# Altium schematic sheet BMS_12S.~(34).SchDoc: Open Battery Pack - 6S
size A3; Author: Morgane Vallée; Revision: 1.0; SheetNumber: 3; SheetTotal: 4
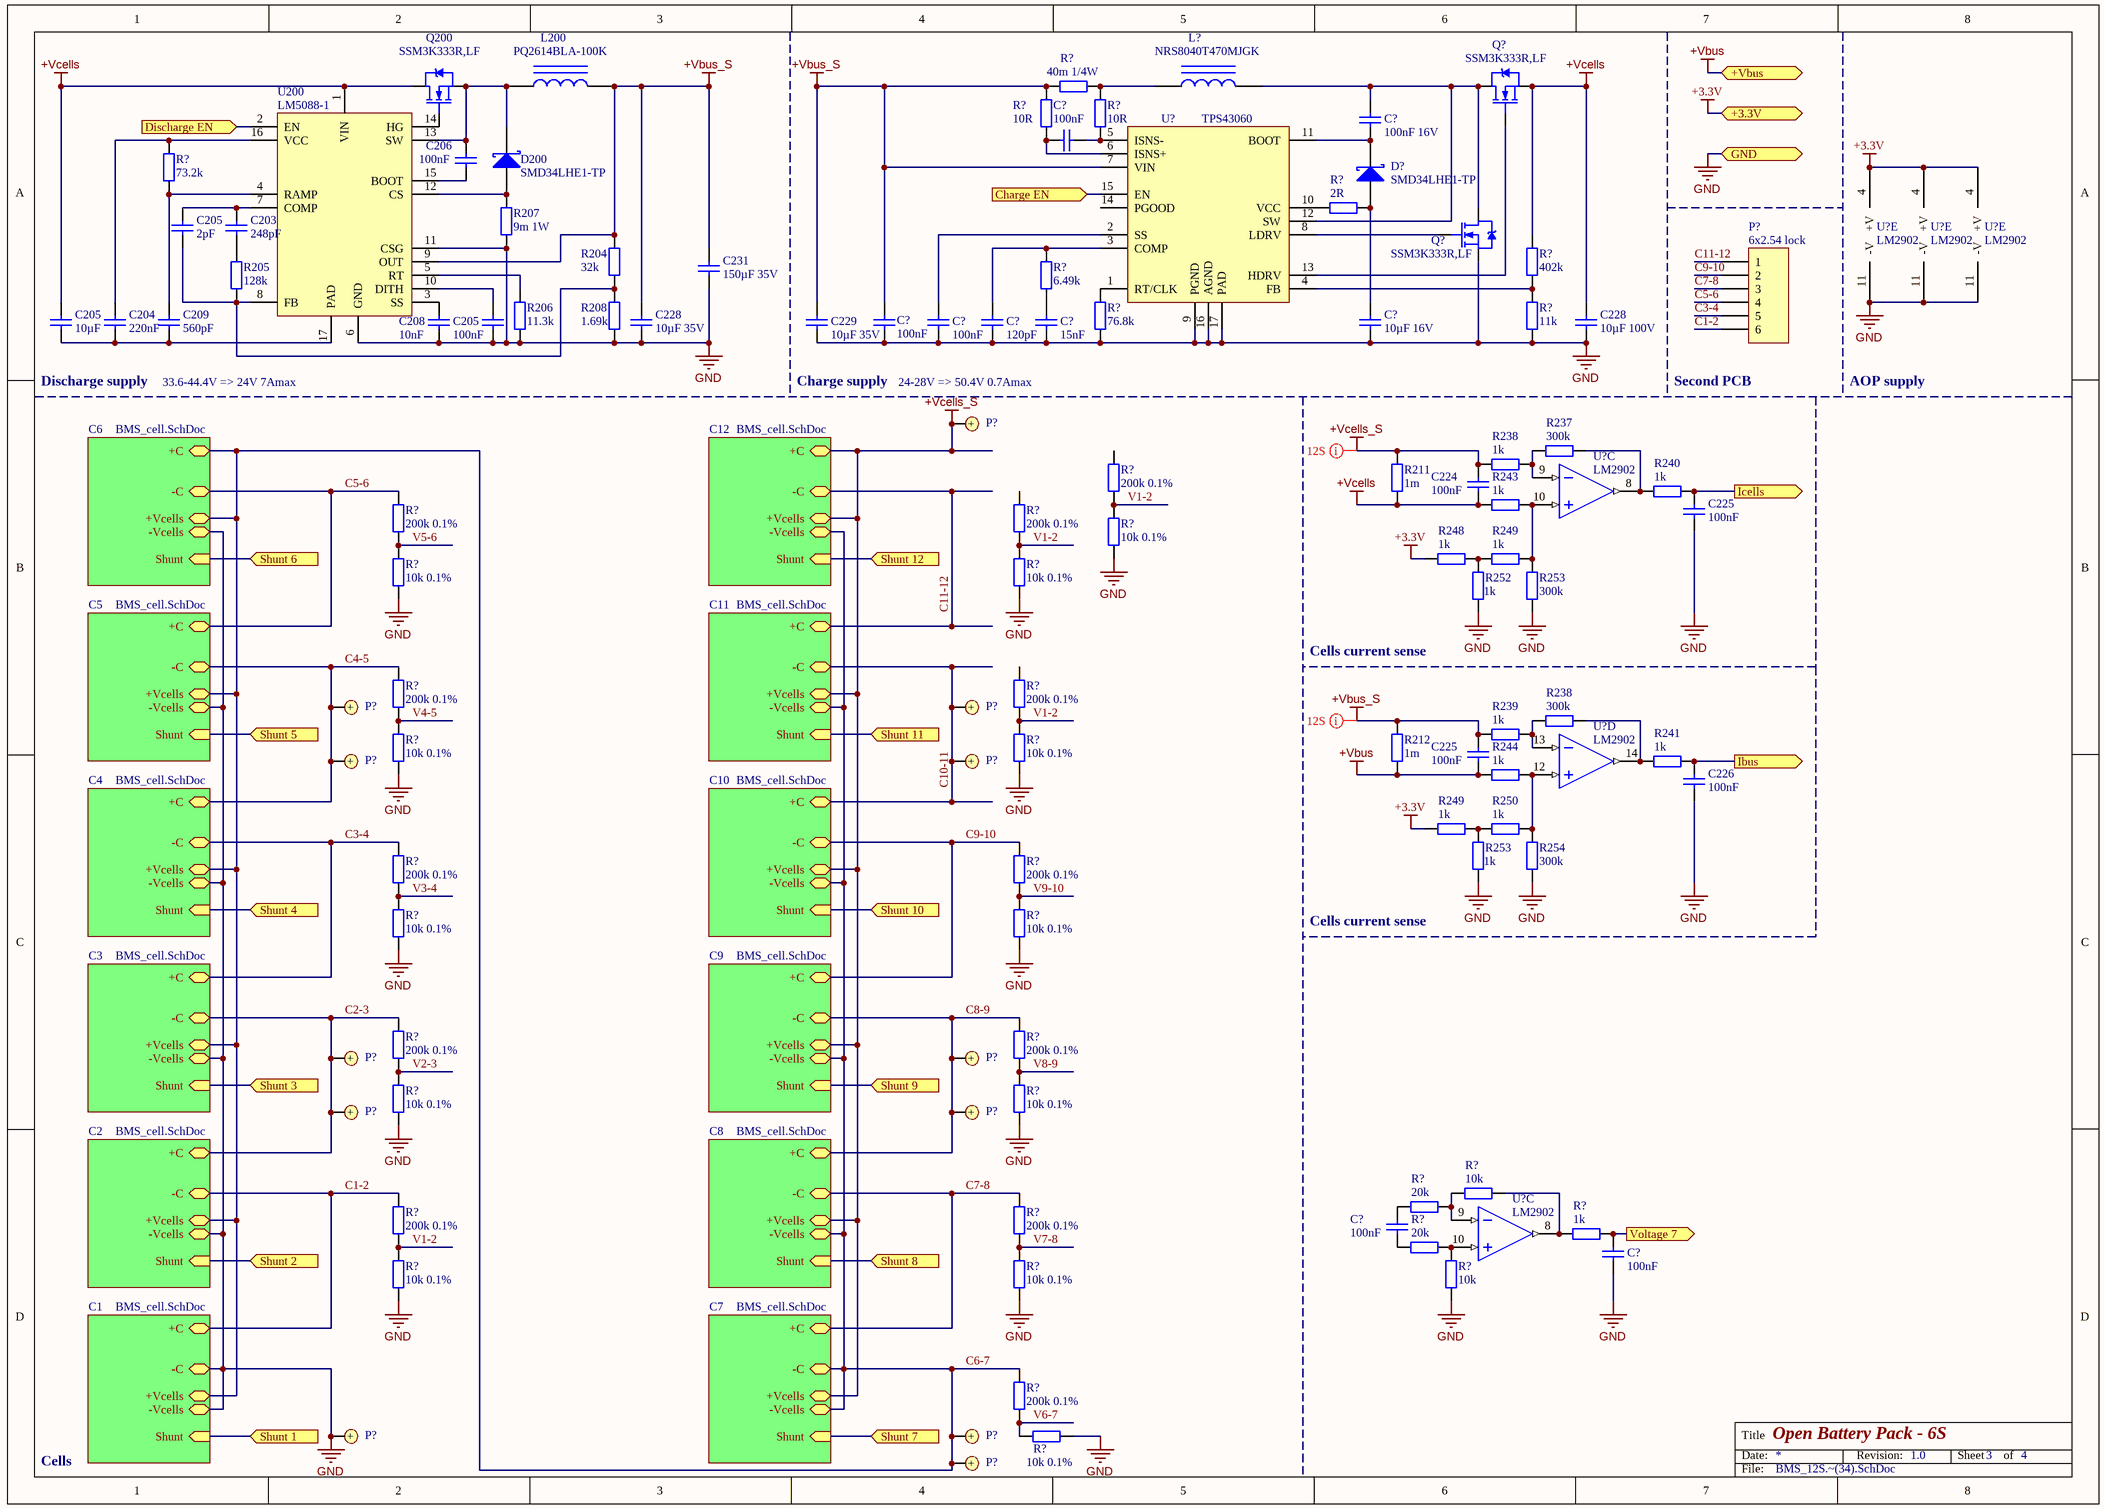
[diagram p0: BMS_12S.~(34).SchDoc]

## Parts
(Parts that share a designator on the sheet are numbered #1, #2 ... from top to bottom, then left to right.)
C203  248pF  [C0603]
C204  220nF  [C0603]
C205#1  2pF  [C0603]
C205#2  10µF  [C0603]
C205#3  100nF  [C0603]
C206  100nF  [C0603]
C208  10nF  [C0603]
C209  560pF  [C0603]
C224  100nF  [C0603]
C225#1  100nF  [C0603]
C225#2  100nF  [C0603]
C226  100nF  [C0603]
C228#1  10µF 35V  [C0603]
C228#2  10µF 100V  [C0603]
C229  10µF 35V  [C0603]
C231  150µF 35V  [C0603]
C?#1  100nF 16V  [C0603]
C?#2  100nF  [C0603]
C?#3  100nF  [C0603]
C?#4  120pF  [C0603]
C?#5  15nF  [C0603]
C?#6  10µF 16V  [C0805]
C?#7  100nF  [C0603]
C?#8  100nF  [C0603]
C?#9  100nF  [C0603]
D200  SMD34LHE1-TP  [SOD-123H]
D?  SMD34LHE1-TP  [SOD-123H]
L200  PQ2614BLA-100K  [SELF_SMD_8x8]
L?  NRS8040T470MJGK  [SELF_SMD_8x8]
P?#1  6x2.54 lock  [MOLEX KK 0022272061]
P?#2  Bat+  [Keystone 241]  (value not drawn)
P?#3  Bat+  [Keystone 241]  (value not drawn)
P?#4  Bat+  [Keystone 241]  (value not drawn)
P?#5  Bat+  [Keystone 241]  (value not drawn)
P?#6  Bat+  [Keystone 241]  (value not drawn)
P?#7  Bat+  [Keystone 241]  (value not drawn)
P?#8  Bat+  [Keystone 241]  (value not drawn)
P?#9  Bat+  [Keystone 241]  (value not drawn)
P?#10  Bat+  [Keystone 241]  (value not drawn)
P?#11  Bat+  [Keystone 241]  (value not drawn)
P?#12  Bat+  [Keystone 241]  (value not drawn)
P?#13  Bat+  [Keystone 241]  (value not drawn)
Q200  SSM3K333R,LF  [TI SOT-23-3 DBZ]
Q?#1  SSM3K333R,LF  [TI SOT-23-3 DBZ]
Q?#2  SSM3K333R,LF  [TI SOT-23-3 DBZ]
R204  32k  [R0603]
R205  128k  [R0603]
R206  11.3k  [R0603]
R207  9m 1W  [R1206]
R208  1.69k  [R0603]
R211  1m  [R1206]
R212  1m  [R1206]
R237  300k  [R0603]
R238#1  1k  [R0603]
R238#2  300k  [R0603]
R239  1k  [R0603]
R240  1k  [R0603]
R241  1k  [R0603]
R243  1k  [R0603]
R244  1k  [R0603]
R248  1k  [R0603]
R249#1  1k  [R0603]
R249#2  1k  [R0603]
R250  1k  [R0603]
R252  1k  [R0603]
R253#1  300k  [R0603]
R253#2  1k  [R0603]
R254  300k  [R0603]
R?#1  10R  [R0603]
R?#2  40m 1/4W  [R1206]
R?#3  10R  [R0603]
R?#4  73.2k  [R0603]
R?#5  2R  [R0603]
R?#6  402k  [R0603]
R?#7  6.49k  [R0603]
R?#8  76.8k  [R0603]
R?#9  11k  [R0603]
R?#10  200k 0.1%  [R0603]
R?#11  200k 0.1%  [R0603]
R?#12  200k 0.1%  [R0603]
R?#13  10k 0.1%  [R0603]
R?#14  10k 0.1%  [R0603]
R?#15  10k 0.1%  [R0603]
R?#16  200k 0.1%  [R0603]
R?#17  200k 0.1%  [R0603]
R?#18  10k 0.1%  [R0603]
R?#19  10k 0.1%  [R0603]
R?#20  200k 0.1%  [R0603]
R?#21  200k 0.1%  [R0603]
R?#22  10k 0.1%  [R0603]
R?#23  10k 0.1%  [R0603]
R?#24  200k 0.1%  [R0603]
R?#25  200k 0.1%  [R0603]
R?#26  10k 0.1%  [R0603]
R?#27  10k 0.1%  [R0603]
R?#28  10k  [R0603]
R?#29  20k  [R0603]
R?#30  200k 0.1%  [R0603]
R?#31  200k 0.1%  [R0603]
R?#32  1k  [R0603]
R?#33  10k 0.1%  [R0603]
R?#34  10k 0.1%  [R0603]
R?#35  20k  [R0603]
R?#36  10k  [R0603]
R?#37  200k 0.1%  [R0603]
R?#38  10k 0.1%  [R0603]
U200  LM5088-1  [TI MSOP-10 DGQ]
U?#1  TPS43060  [TI WQFN-16 RGH]
U?#2  LM2902  [Atmel SO-14 14S1]  (part E of 5)
U?#3  LM2902  [Atmel SO-14 14S1]  (part E of 5)
U?#4  LM2902  [Atmel SO-14 14S1]  (part E of 5)
U?#5  LM2902  [Atmel SO-14 14S1]  (part C of 5)
U?#6  LM2902  [Atmel SO-14 14S1]  (part D of 5)
U?#7  LM2902  [Atmel SO-14 14S1]  (part C of 5)

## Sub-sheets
C1 = BMS_cell.SchDoc: -C, +C, +Vcells, -Vcells, Shunt (in)
C2 = BMS_cell.SchDoc: -C, +C, +Vcells, -Vcells, Shunt (in)
C3 = BMS_cell.SchDoc: -C, +C, +Vcells, -Vcells, Shunt (in)
C4 = BMS_cell.SchDoc: -C, +C, +Vcells, -Vcells, Shunt (in)
C5 = BMS_cell.SchDoc: -C, +C, +Vcells, -Vcells, Shunt (in)
C6 = BMS_cell.SchDoc: -C, +C, +Vcells, -Vcells, Shunt (in)
C7 = BMS_cell.SchDoc: -C, +C, +Vcells, -Vcells, Shunt (in)
C8 = BMS_cell.SchDoc: -C, +C, +Vcells, -Vcells, Shunt (in)
C9 = BMS_cell.SchDoc: -C, +C, +Vcells, -Vcells, Shunt (in)
C10 = BMS_cell.SchDoc: -C, +C, +Vcells, -Vcells, Shunt (in)
C11 = BMS_cell.SchDoc: -C, +C, +Vcells, -Vcells, Shunt (in)
C12 = BMS_cell.SchDoc: -C, +C, +Vcells, -Vcells, Shunt (in)

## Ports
+3.3V, +Vbus, Charge EN (in), Discharge EN (in), GND, Ibus (out), Icells (out), Shunt 1 (in), Shunt 2 (in), Shunt 3 (in), Shunt 4 (in), Shunt 5 (in), Shunt 6 (in), Shunt 7 (in), Shunt 8 (in), Shunt 9 (in), Shunt 10 (in), Shunt 11 (in), Shunt 12 (in), Voltage 7 (out)

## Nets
+3.3V: R248.2 R249#2.2 U?#2.4(+V) U?#3.4(+V) U?#4.4(+V) ; port +3.3V
+Vbus: C225#2.2 R212.1 R244.2 ; port +Vbus
+Vbus_S: C225#2.1 C228#1.1 C229.1 C231.1 C?#7.2 L200.2 R204.2 R212.2 R239.1 R?#1.1 R?#2.2 U200.9(OUT) U?#1.7(VIN)
+Vcells: C205#2.1 C224.2 C228#2.1 Q200.3(D) Q?#1.2(S) R211.1 R243.2 R?#6.2 U200.1(VIN)
+Vcells_S: C224.1 P?#2.1 R211.2 R238#1.1 ; sheet C7/+Vcells, sheet C8/+Vcells, sheet C9/+Vcells, sheet C10/+Vcells, sheet C11/+Vcells, sheet C12/+C, sheet C12/+Vcells
GND: C205#3.2 C208.2 C225#1.2 C226.2 C228#1.2 C228#2.2 C229.2 C231.2 C?#3.2 C?#4.2 C?#5.2 C?#6.2 C?#7.1 C?#9.2 P?#11.1 Q?#2.2(S) R206.1 R207.1 R208.1 R252.2 R253#1.1 R253#2.2 R254.1 R?#8.1 R?#9.1 R?#13.2 R?#14.2 R?#15.2 R?#18.2 R?#19.2 R?#22.2 R?#23.2 R?#26.2 R?#27.2 R?#33.2 R?#34.2 R?#36.2 R?#38.2 U200.6(GND) U200.11(CSG) U?#1.9(PGND) U?#1.16(AGND) U?#1.17(PAD) U?#2.11(-V) U?#3.11(-V) U?#4.11(-V) ; port GND, sheet C1/-C, sheet C1/-Vcells, sheet C2/-Vcells, sheet C3/-Vcells, sheet C4/-Vcells, sheet C5/-Vcells, sheet C6/-Vcells
C1-2: P?#1.6 R?#30.1 ; sheet C1/+C, sheet C2/-C
C2-3: P?#7.1 P?#9.1 R?#24.1 ; sheet C2/+C, sheet C3/-C
C3-4: P?#1.5 R?#20.1 ; sheet C3/+C, sheet C4/-C
C4-5: P?#3.1 P?#5.1 R?#16.1 ; sheet C4/+C, sheet C5/-C
C5-6: P?#1.4 R?#11.1 ; sheet C5/+C, sheet C6/-C
C6-7: P?#12.1 P?#13.1 R?#37.1 ; sheet C1/+Vcells, sheet C2/+Vcells, sheet C3/+Vcells, sheet C4/+Vcells, sheet C5/+Vcells, sheet C6/+C, sheet C6/+Vcells, sheet C7/-C, sheet C7/-Vcells, sheet C8/-Vcells, sheet C9/-Vcells, sheet C10/-Vcells, sheet C11/-Vcells, sheet C12/-Vcells
C7-8: P?#1.3 R?#31.1 ; sheet C7/+C, sheet C8/-C
C8-9: P?#8.1 P?#10.1 R?#25.1 ; sheet C8/+C, sheet C9/-C
C9-10: P?#1.2 R?#21.1 ; sheet C9/+C, sheet C10/-C
C10-11: P?#4.1 P?#6.1 ; sheet C10/+C, sheet C11/-C
C11-12: P?#1.1 ; sheet C11/+C, sheet C12/-C
Charge EN: U?#1.15(EN) ; port Charge EN
Discharge EN: U200.2(EN) ; port Discharge EN
Ibus: C226.1 R241.1 ; port Ibus
Icells: C225#1.1 R240.1 ; port Icells
Shunt 1: port Shunt 1, sheet C1/Shunt
Shunt 2: port Shunt 2, sheet C2/Shunt
Shunt 3: port Shunt 3, sheet C3/Shunt
Shunt 4: port Shunt 4, sheet C4/Shunt
Shunt 5: port Shunt 5, sheet C5/Shunt
Shunt 6: port Shunt 6, sheet C6/Shunt
Shunt 7: port Shunt 7, sheet C7/Shunt
Shunt 8: port Shunt 8, sheet C8/Shunt
Shunt 9: port Shunt 9, sheet C9/Shunt
Shunt 10: port Shunt 10, sheet C10/Shunt
Shunt 11: port Shunt 11, sheet C11/Shunt
Shunt 12: port Shunt 12, sheet C12/Shunt
V1-2: R?#10.2 R?#12.2 R?#13.1 R?#15.1 R?#17.2 R?#19.1 R?#30.2 R?#33.1
V2-3: R?#24.2 R?#26.1
V3-4: R?#20.2 R?#22.1
V4-5: R?#16.2 R?#18.1
V5-6: R?#11.2 R?#14.1
V6-7: R?#37.2 R?#38.1
V7-8: R?#31.2 R?#34.1
V8-9: R?#25.2 R?#27.1
V9-10: R?#21.2 R?#23.1
Voltage 7: C?#9.1 R?#32.1 ; port Voltage 7
NetC203_1: C203.1 C205#1.1 U200.7(COMP)
NetC203_2: C203.2 R205.2
NetC204_1: C204.1 R?#4.2 U200.16(VCC)
NetC204_2: C204.2 C205#2.2 C209.2 U200.17(PAD)
NetC205#1_2: C205#1.2 R204.1 R205.1 R208.2 U200.8(FB)
NetC205#3_1: C205#3.1 U200.10(DITH)
NetC206_1: C206.1 D200.3(K) L200.1 Q200.2(S) U200.13(SW)
NetC206_2: C206.2 U200.15(BOOT)
NetC208_1: C208.1 U200.3(SS)
NetC209_1: C209.1 R?#4.1 U200.4(RAMP)
NetC?#1_1: C?#1.1 L?.2 Q?#1.3(D) Q?#2.3(D) U?#1.12(SW)
NetC?#1_2: C?#1.2 D?.3(K) U?#1.11(BOOT)
NetC?#2_1: C?#2.1 R?#3.2 U?#1.5(ISNS-)
NetC?#2_2: C?#2.2 R?#1.2 U?#1.6(ISNS+)
NetC?#3_1: C?#3.1 U?#1.2(SS)
NetC?#4_1: C?#4.1 R?#7.2 U?#1.3(COMP)
NetC?#5_1: C?#5.1 R?#7.1
NetC?#6_1: C?#6.1 D?.1(A) R?#5.1
NetC?#8_1: C?#8.1 R?#29.1
NetC?#8_2: C?#8.2 R?#35.2
NetD200_1: D200.1(A) R207.2 U200.12(CS)
NetL?_1: L?.1 R?#2.1 R?#3.1
NetQ200_1: Q200.1(G) U200.14(HG)
NetQ?#1_1: Q?#1.1(G) U?#1.13(HDRV)
NetQ?#2_1: Q?#2.1(G) U?#1.8(LDRV)
NetR206_2: R206.2 U200.5(RT)
NetR237_1: R237.1 R240.2 U?#5.8(OUT)
NetR237_2: R237.2 R238#1.2 U?#5.9(IN-)
NetR238#2_1: R238#2.1 R241.2 U?#6.14(OUT)
NetR238#2_2: R238#2.2 R239.2 U?#6.13(IN-)
NetR243_1: R243.1 R249#1.1 R253#1.2 U?#5.10(IN+)
NetR244_1: R244.1 R250.1 R254.2 U?#6.12(IN+)
NetR248_1: R248.1 R249#1.2 R252.1
NetR249#2_1: R249#2.1 R250.2 R253#2.1
NetR?#5_2: R?#5.2 U?#1.10(VCC)
NetR?#6_1: R?#6.1 R?#9.2 U?#1.4(FB)
NetR?#8_2: R?#8.2 U?#1.1(RT/CLK)
NetR?#28_1: R?#28.1 R?#29.2 U?#7.9(IN-)
NetR?#28_2: R?#28.2 R?#32.2 U?#7.8(OUT)
NetR?#35_1: R?#35.1 R?#36.1 U?#7.10(IN+)

Not connected (* = marked no-connect by the designer): R?#10 1; R?#12 1; R?#17 1; U?#1 14(PGOOD)

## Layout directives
net class 12S: +Vbus_S, +Vcells_S

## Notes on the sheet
- Discharge supply
- 33.6-44.4V => 24V 7Amax
- Charge supply
- 24-28V => 50.4V 0.7Amax
- (near P?#1) Second PCB
- AOP supply
- Cells current sense
- (near R253#2) Cells current sense
- Cells

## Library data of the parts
C203 C204 C205#1-C205#3 C206 C208 C209 C224 C225#1 C225#2 C226 C228#1 C228#2 C229 C231 C?#1-C?#9 = Cap: Capacitor
D200 D? = Diode BAT17
L200 L? = Inductor Iron: Magnetic-Core Inductor
P?#1 = Header 6: Header, 6-Pin
P?#2-P?#13 = Bat+: Battery contact +
Q200 Q?#1 Q?#2 = MOSFET_N
R204-R208 R211 R212 R237 R238#1 R238#2 R239-R241 R243 R244 R248 R249#1 R249#2 R250 R252 R253#1 R253#2 R254 R?#1-R?#38 = Res2: Resistor
U200 = LM5088-1: Wide Input Range Non-Synchronous Buck Controller
U?#1 = TPS43060: Low Quiescent Current Synchronous Boost  DC-DC Controller With Wide VIN Range
U?#2-U?#7 = LM2902: Low-power quad operational amplifiers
